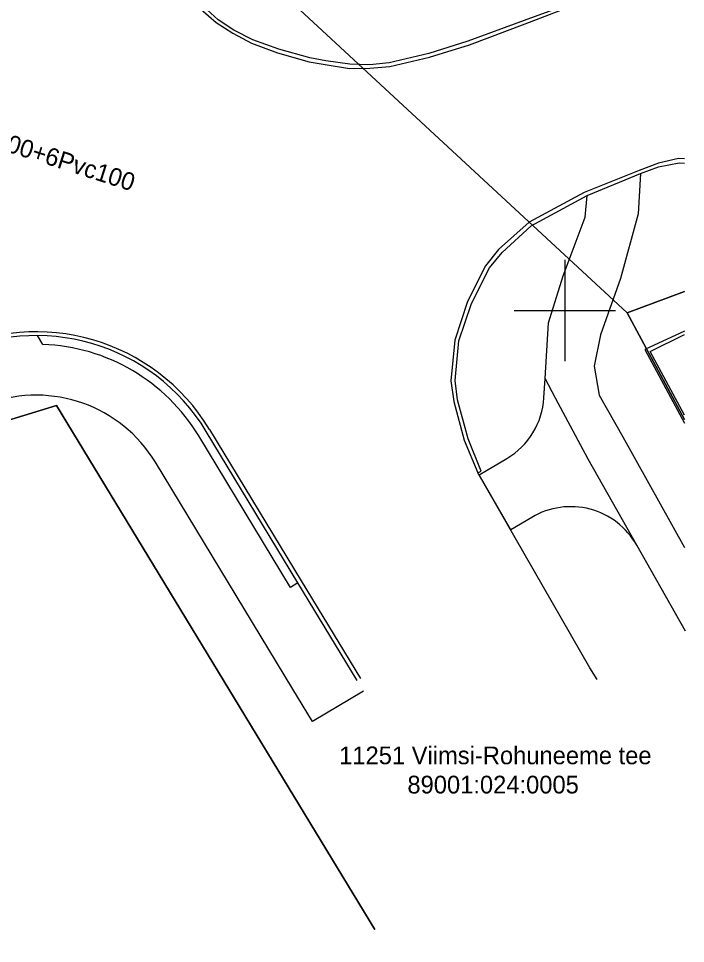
# Model space of a CAD drawing. Extents: x 546339 to 546593, y 6597108 to 6597251.
# Drawn here: x 546528.43 to 546554.76, y 6597175.02 to 6597211.53 of the extents above; entities that cross this region are included whole.
import ezdxf

# ---------------------------------------------------------------- set-up
doc = ezdxf.new("R2010")
doc.units = 0
for name, color, linetype in [('PIIR', 7, 'Continuous'), ('SITRASS', 7, 'Continuous'), ('TEE', 7, 'Continuous'), ('VORK', 7, 'Continuous')]:
    doc.layers.add(name, color=color, linetype=linetype)

msp = doc.modelspace()

# ---------------------------------------------------------------- linework, layer by layer
at = {"layer": 'PIIR'}
for points in [[(546554.719, 6597195.706), (546552.45, 6597199.91), (546537.23, 6597214.01), (546528.578, 6597228.838)], [(546508.483, 6597226.076), (546518.84, 6597207.6), (546510.07, 6597205.36), (546515.77, 6597191.92), (546529.93, 6597196.26), (546542.493, 6597175.58)], [(546554.719, 6597219.467), (546537.23, 6597214.01), (546552.45, 6597199.91), (546554.719, 6597200.75)], [(546554.719, 6597200.75), (546552.45, 6597199.91), (546554.719, 6597195.706)], [(546542.493, 6597175.58), (546529.93, 6597196.26), (546515.77, 6597191.92), (546505.65, 6597188.82), (546512.531, 6597166.376)]]:
    msp.add_lwpolyline(points, dxfattribs=at)
at = {"layer": 'TEE'}
for p, q in [((546529.384, 6597198.662), (546529.174, 6597199.012)), ((546535.97, 6597195.308), (546539.59, 6597189.333)), ((546539.461, 6597189.255), (546535.842, 6597195.23)), ((546547.861, 6597191.345), (546546.615, 6597193.513)), ((546541.793, 6597185.406), (546539.461, 6597189.255)), ((546539.59, 6597189.333), (546541.922, 6597185.483)), ((546542.05, 6597184.977), (546540.037, 6597183.779))]:
    msp.add_line(p, q, dxfattribs=at)
for points in [[(546535.622, 6597211.888), (546536.225, 6597211.372), (546536.884, 6597210.941), (546537.622, 6597210.546), (546538.656, 6597210.167), (546539.898, 6597209.813), (546540.535, 6597209.707), (546541.491, 6597209.555), (546542.3, 6597209.559), (546543.087, 6597209.625), (546544.655, 6597210.001), (546546.225, 6597210.484), (546548.433, 6597211.313), (546550.013, 6597211.921)], [(546549.94, 6597212.016), (546548.39, 6597211.446), (546546.159, 6597210.626), (546544.629, 6597210.15), (546543.057, 6597209.775), (546542.295, 6597209.693), (546541.512, 6597209.719), (546540.565, 6597209.857), (546539.933, 6597209.967), (546538.706, 6597210.311), (546537.674, 6597210.685), (546536.925, 6597211.071), (546536.307, 6597211.468), (546535.725, 6597211.995)], [(546554.719, 6597205.987), (546554.477, 6597206.003), (546553.693, 6597205.816), (546552.927, 6597205.529), (546550.762, 6597204.656), (546548.59, 6597203.482), (546547.379, 6597202.416), (546546.868, 6597201.767), (546546.153, 6597200.359), (546545.649, 6597198.832), (546545.499, 6597197.231), (546545.616, 6597196.416), (546546.022, 6597194.889), (546546.565, 6597193.6), (546546.698, 6597193.657)], [(546546.698, 6597193.657), (546546.175, 6597194.938), (546545.761, 6597196.471), (546545.668, 6597197.245), (546545.806, 6597198.805), (546546.305, 6597200.277), (546547.025, 6597201.681), (546547.525, 6597202.288), (546548.666, 6597203.338), (546550.881, 6597204.546), (546552.981, 6597205.413), (546553.696, 6597205.673), (546554.505, 6597205.831), (546554.719, 6597205.82)], [(546552.981, 6597205.413), (546552.886, 6597203.812), (546552.196, 6597201.263), (546551.406, 6597199.039), (546551.146, 6597197.806), (546551.347, 6597196.666), (546552.283, 6597195.017), (546554.719, 6597190.647)], [(546554.758, 6597187.342), (546550.912, 6597194.132), (546549.62, 6597196.541), (546549.216, 6597197.322), (546549.35, 6597199.515), (546549.926, 6597201.37), (546550.791, 6597203.683), (546550.881, 6597204.546)], [(546554.719, 6597199.193), (546553.151, 6597198.457), (546554.719, 6597195.557)], [(546554.719, 6597195.873), (546553.359, 6597198.389), (546554.719, 6597199.055)], [(546549.169, 6597196.56), (546549.169, 6597196.56), (546549.216, 6597197.322)], [(546539.461, 6597189.255), (546539.164, 6597189.078), (546535.546, 6597195.051)], [(546546.615, 6597193.513), (546547.71, 6597194.165), (546547.71, 6597194.165)], [(546540.037, 6597183.779), (546539.262, 6597185.058), (546533.832, 6597194.012)], [(546551.267, 6597185.436), (546550.987, 6597185.905), (546546.565, 6597193.6)], [(546548.689, 6597191.838), (546548.689, 6597191.838), (546547.861, 6597191.345)]]:
    msp.add_lwpolyline(points, dxfattribs=at)
for centre, radius, start, end in [((546529.128, 6597191.162), 8, 31.2085, 116.4253), ((546529.128, 6597191.162), 7.85, 31.2085, 116.4253), ((546529.128, 6597191.162), 7.504, 31.2085, 88.0395), ((546529.128, 6597191.162), 5.5, 31.2085, 109.6372), ((546546.175, 6597196.743), 3, 300.7652, 356.5034), ((546550.223, 6597189.261), 3, 29.5276, 120.7652)]:
    msp.add_arc(centre, radius, start, end, dxfattribs=at)
at = {"layer": 'VORK'}
for p, q in [((546550, 6597202), (546550, 6597198)), ((546548, 6597200), (546552, 6597200))]:
    msp.add_line(p, q, dxfattribs=at)

# ---------------------------------------------------------------- texts
at = {"layer": 'PIIR'}
for s, p in [('11251 Viimsi-Rohuneeme tee', (546541.086, 6597182.097)), ('89001:024:0005', (546543.78, 6597180.944))]:
    msp.add_text(s, height=0.7, dxfattribs=at).set_placement(p)
at = {"layer": 'SITRASS'}
msp.add_text(' 6Asb100+6Pvc100 ', height=0.7, rotation=342.3016, dxfattribs=at).set_placement((546525.128, 6597207.177))

doc.saveas('drawing.dxf')
